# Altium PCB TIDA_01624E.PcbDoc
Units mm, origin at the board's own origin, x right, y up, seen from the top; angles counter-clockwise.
Board outline 19.05 x 30.89 mm, 2 copper layers (Top Layer, Bottom Layer), stack 0.239 mm thick; 33 components, 19 nets, 97 pads, 129 vias.
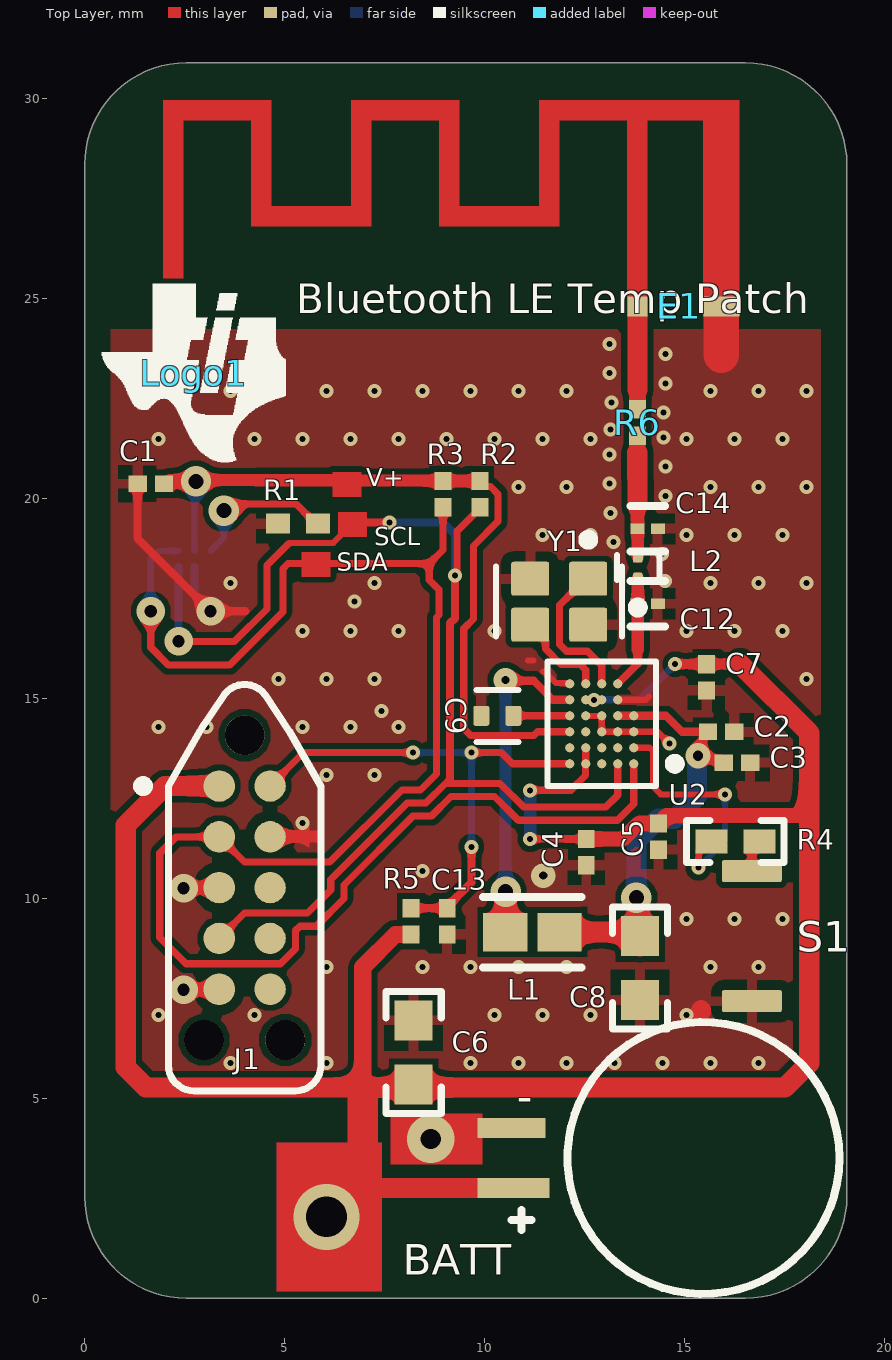
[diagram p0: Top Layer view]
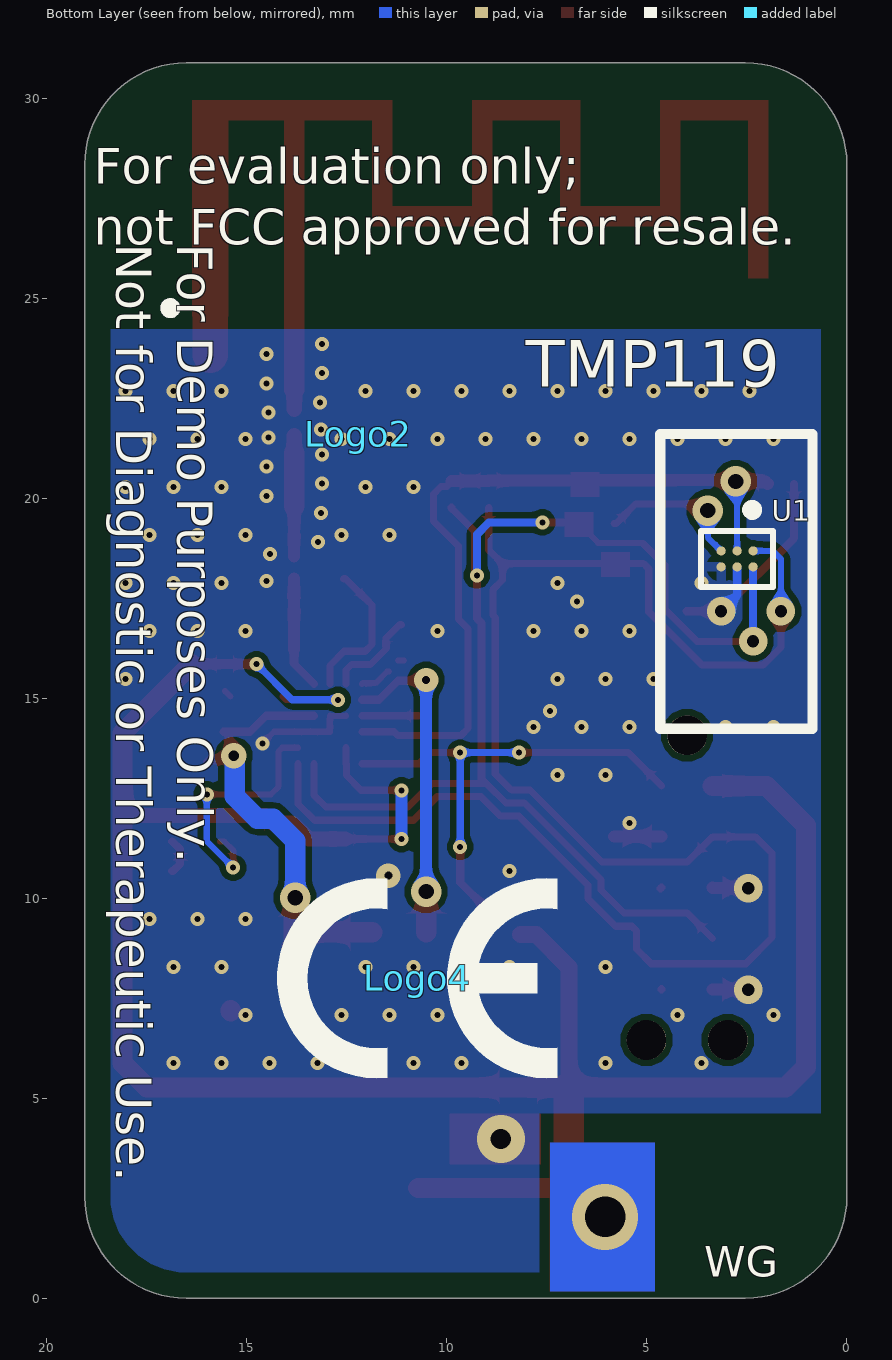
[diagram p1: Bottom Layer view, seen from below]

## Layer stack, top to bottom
Top Solder: solder mask 0.0254, Polymide, Dk 3.3
Top Layer: signal copper 0.0178
Stiffener: dielectric 0.127, Polyimide, Dk 4.2
Flex Substrate: core 0.0762, Polymide, Dk 3.3
Bottom Layer: signal copper 0.0178
Bottom Solder: solder mask 0.0254, Polyimide, Dk 3.3

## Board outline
0,2.54 0,28.345 cw(c2.54,28.345) 2.54,30.885 16.51,30.885 cw(c16.51,28.345) 19.05,28.345 19.05,2.54 cw(c16.51,2.54) 16.51,0 2.54,0 cw(c2.54,2.54)

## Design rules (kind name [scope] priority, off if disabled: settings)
AcuteAngle [All] p1: minimum=4.50000000000000E+0001 checktracksonly=FALSE
AssemblyTestPointUsage [All] p1: valid=2
BoardOutlineClearance BoardOutlineClearance_MountingHoles [OnCopper and InComponentClass('Mounting Holes')] p1 off: gap=1.016 ignorepadtopadclearanceinfootprint=FALSE
BoardOutlineClearance BoardOutlineClearance_Poly [OnCopper and IsPoly] p2: gap=0.635 ignorepadtopadclearanceinfootprint=FALSE
BoardOutlineClearance [OnCopper and Not InComponentClass('Logo') and not InComponentClass('FiducialMark') and not InRegion(1000,500,4000,800) and not InPoly] p3 off: gap=1.016 ignorepadtopadclearanceinfootprint=FALSE
Clearance Clearance_2 [InNamedPolygon('GND_L01_P002') vs InComponent('E1')] p1: gap=0 ignorepadtopadclearanceinfootprint=FALSE
Clearance Clearance_Keepouts [((IsTrack Or IsArc) And Not InPoly) And IsFree and IsKeepOut vs ((IsTrack Or IsArc) And Not InPoly) And IsFree and IsKeepOut] p2: gap=0 ignorepadtopadclearanceinfootprint=FALSE
Clearance Clearance_Poly [InPolygon] p3 off: gap=0.635 ignorepadtopadclearanceinfootprint=FALSE except(0: Arc-Hole Track-Hole SMDPad-Hole THPad-Hole Via-Hole Fill-Hole Poly-Hole Region-Hole Text-Hole)
Clearance [All] p4: gap=0.15 ignorepadtopadclearanceinfootprint=FALSE
ComponentClearance ComponentClearance_ant [InComponent('R6') vs InComponent('R7')] p1: gap=0 collisioncheckmode=3 verticalgap=0 showdistances=FALSE
ComponentClearance ComponentClearance_MountingHoles_FiducialMarks [InComponentClass('Mounting Holes') vs InComponentClass('FiducialMark')] p2: gap=1.27 collisioncheckmode=3 verticalgap=0.254 showdistances=FALSE
ComponentClearance ComponentClearance_Shunt [InComponentClass('Header') vs InComponentClass('Shunt')] p3: gap=0 collisioncheckmode=3 verticalgap=0 showdistances=FALSE
ComponentClearance ComponentClearance_Logo [InComponentClass('Logo')] p4: gap=0 collisioncheckmode=3 verticalgap=0 showdistances=FALSE
ComponentClearance ComponentClearance_ScrewToNut [(HasFootprint('NY PMS 440 0025 PH')) vs (HasFootprint('Keystone_1902C'))] p5: gap=0.127 collisioncheckmode=3 verticalgap=0.254 showdistances=FALSE
ComponentClearance ComponentClearance_MountingHoles [InComponentClass('Mounting Holes')] p6: gap=6.35 collisioncheckmode=3 verticalgap=2540 showdistances=FALSE
ComponentClearance ComponentClearance_SmallPassives [HasFootprint('0201*') or HasFootprint('0402*') or HasFootprint('0508') or HasFootprint('0603*') or HasFootprint('0612') or HasFootprint('0805*') or HasFootprint('0815*') or HasFootprint('0830*') or HasFootprint('1206*') or HasFootprint('1210*') or HasFootprint('1808*') or HasFootprint('1812*') or HasFootprint('1825*') or HasFootprint('2010*') or HasFootprint('2220*') or HasFootprint('2225*') or HasFootprint('2512*') or HasFootprint('2728*') or HasFootprint('3518*') vs HasFootprint('0201*') or HasFootprint('0402*') or HasFootprint('0508') or HasFootprint('0603*') or HasFootprint('0612') or HasFootprint('0805*') or HasFootprint('0815*') or HasFootprint('0830*') or HasFootprint('1206*') or HasFootprint('1210*') or HasFootprint('1808*') or HasFootprint('1812*') or HasFootprint('1825*') or HasFootprint('2010*') or HasFootprint('2220*') or HasFootprint('2225*') or HasFootprint('2512*') or HasFootprint('2728*') or HasFootprint('3518*')] p7: gap=0.38 collisioncheckmode=3 verticalgap=0.254 showdistances=FALSE
ComponentClearance ComponentClearance_THtoSMT [IsThruComponent vs IsSMTComponent] p8: gap=1.016 collisioncheckmode=3 verticalgap=0.762 showdistances=FALSE
ComponentClearance ComponentClearance_THtoTH [IsThruComponent vs IsThruComponent] p9: gap=0.381 collisioncheckmode=3 verticalgap=0.762 showdistances=FALSE
ComponentClearance [All] p10: gap=0.381 collisioncheckmode=3 verticalgap=0.254 showdistances=FALSE
DiffPairsRouting [All] p1: maxlimit=2.54 minlimit=0.254 mostfreqgap=0.254 substack1={58F8C5E5-8A2A-45DE-ADA6-7FDF080C0BA6} toplayer_{58f8c5e5-8a2a-45de-ada6-7fdf080c0ba6}_minwidth=0.381 toplayer_{58f8c5e5-8a2a-45de-ada6-7fdf080c0ba6}_maxwidth=0.381 toplayer_{58f8c5e5-8a2a-45de-ada6-7fdf080c0ba6}_prefwidth=0.381 bottomlayer_{58f8c5e5-8a2a-45de-ada6-7fdf080c0ba6}_minwidth=0.381 bottomlayer_{58f8c5e5-8a2a-45de-ada6-7fdf080c0ba6}_maxwidth=0.381 bottomlayer_{58f8c5e5-8a2a-45de-ada6-7fdf080c0ba6}_prefwidth=0.381 toplayer_minwidth=0.381 toplayer_maxwidth=0.381 toplayer_prefwidth=0.381 bottomlayer_minwidth=0.381 bottomlayer_maxwidth=0.381 bottomlayer_prefwidth=0.381 maxuncoupledlength=25.4
FabricationTestPointUsage TestPointUsage [All] p1: valid=2 allowmultiple=FALSE
FabricationTestpoint Testpoint [All] p1: side=3 testpointundercomponent=TRUE minsize=1.016 maxsize=2.54 preferedsize=1.524 minholesize=0 maxholesize=1.016 preferedholesize=0.813 testpointgrid=0.025 allowsidetop=TRUE allowsidebottom=TRUE usegrid=TRUE gridtolerance=0
FanoutControl Fanout_LCC [IsLCC] p1: bgadir=Out bgaviamode=Centered fanoutstyle=Auto fanoutdirection=Alternating viagrid=0.025 // Fanout_LCC (Default Rule)
FanoutControl Fanout_BGA [IsBGA] p2: bgadir=Out bgaviamode=Centered fanoutstyle=Auto fanoutdirection=Alternating viagrid=0.025 // Fanout_BGA (Default Rule)
FanoutControl Fanout_Default [All] p4: bgadir=Out bgaviamode=Centered fanoutstyle=Auto fanoutdirection=Alternating viagrid=0.025 // Fanout_Default (Default Rule)
FanoutControl Fanout_Small [(CompPinCount < 5)] p5: bgadir=Out bgaviamode=Centered fanoutstyle=Auto fanoutdirection=OutThenIn viagrid=0.025 // Fanout_Small (Default Rule)
HoleSize [All] p1: absolutevalues=TRUE maxlimit=6.375 minlimit=0.15 maxpercent=80.000 minpercent=20.000
MinimumAnnularRing MinimumAnnularRing_ThermalPadVias [IsVia and InAnyComponent] p1: minimumring=0.15
MinimumAnnularRing [All] p2: minimumring=0.1
MinimumSolderMaskSliver MinimumSolderMaskSliver_Logo [InComponentClass('Logo') vs InComponentClass('Logo')] p1: minsoldermaskwidth=0.018
MinimumSolderMaskSliver [All] p2: minsoldermaskwidth=0.051
PlaneConnect [All] p1: planeconnectstyle=Relief reliefexpansion=0.254 reliefentries=4 reliefconductorwidth=0.254 reliefairgap=0.254
PolygonConnect [All] p1: thpad.connectstyle=Relief thpad.reliefconductorwidth=0.254 thpad.reliefentries=4 thpad.polygonreliefangle="90 Angle" thpad.airgapwidth=0.254 smdpad.connectstyle=Relief smdpad.reliefconductorwidth=0.254 smdpad.reliefentries=4 smdpad.polygonreliefangle="90 Angle" smdpad.airgapwidth=0.254 via.connectstyle=Direct via.reliefconductorwidth=0.254 via.reliefentries=4 via.polygonreliefangle="90 Angle" via.airgapwidth=0.254
RoutingVias ThermalPadVias [IsVia and InAnyComponent] p1: holewidth=0.2 width=0.5 viastyle="Through Hole" minholewidth=0.2 minwidth=0.5 maxholewidth=0.33 maxwidth=0.6
RoutingVias [All] p2: holewidth=0.305 width=0.711 viastyle="Through Hole" minholewidth=0.15 minwidth=0.35 maxholewidth=1.016 maxwidth=1.651
ShortCircuit NoNet [IsComponentVia and not InAnyNet vs IsComponentPad and not InAnyNet] p1: allowed=TRUE
ShortCircuit [All] p2: allowed=FALSE
SilkToBoardRegionClearance [Not ((IsComment or IsDesignator) And (Hide <> 'False')) and not InRegion(1000,500,4000,800)] p1:
SilkToSilkClearance SilkToSilkClearance_Pb-FreeLogo [HasFootprint('FCC_disclaimer') vs HasFootprint('TI_Symbol_Overlay_Small')] p1: silktosilkclearance=0
SilkToSilkClearance SilkToSilkClearance_Pb-FreeLogo_1 [(HasFootprint('Pb-Free_Overlay_Medium') OR HasFootprint('Pb-Free_Overlay_Small')) vs (HasFootprint('Pb-Free_Overlay_Medium') OR HasFootprint('Pb-Free_Overlay_Small'))] p2: silktosilkclearance=0
SilkToSilkClearance [All] p3: silktosilkclearance=0.102
SilkToSolderMaskClearance "Silk to Solder Mask Opening" [All] p1: minsilkscreentomaskgap=0.038 clearancetoexposedcopper=FALSE
SolderMaskExpansion SolderMaskExpansion_via [IsVia] p1: expansion=-0.203 istentingtop=FALSE
SolderMaskExpansion [All] p2: expansion=0.05 istentingtop=FALSE
Width [All] p1: maxlimit=0.889 minlimit=0.089 preferedwidth=0.203 substack1={58F8C5E5-8A2A-45DE-ADA6-7FDF080C0BA6} toplayer_{58f8c5e5-8a2a-45de-ada6-7fdf080c0ba6}_minwidth=0.102 bottomlayer_{58f8c5e5-8a2a-45de-ada6-7fdf080c0ba6}_minwidth=0.102 checkconnectedcopper=TRUE
14 further rules are at their usual default settings.

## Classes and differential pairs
component class AssemblyNote: ZZ1 ZZ2 ZZ3
component class Logo: Logo1

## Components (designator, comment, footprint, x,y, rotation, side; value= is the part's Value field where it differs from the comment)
BATT "MS621FE-FL11E" SEIK-MS621FE-FL11E-2_V 15.465,3.505 r180 top
C1 "GRM033C71A104KE14D" 0201 1.648,20.361 r0 top value=0.1uF
C2 "GRM033C71A104KE14D" 0201 15.91,14.162 r180 top value=0.1uF
C3 "GRM033C71A104KE14D" 0201 16.303,13.386 r180 top value=0.1uF
C4 "GRM033C71A104KE14D" 0201 12.535,11.151 r90 top value=0.1uF
C5 "GRM033C71A104KE14D" 0201 14.344,11.54 r90 top value=0.1uF
C6 "GRM188Z71A106KA73D" 0603 8.217,6.147 r270 top
C7 "GRM033C71A104KE14D" 0201 15.541,15.524 r90 top value=0.1uF
C8 "GRM188Z71A106KA73D" 0603 13.879,8.255 r90 top
C9 "GRM155Z71A105KE01D" FP-GRM155Z71A105KE01D_0402-MFG 10.31,14.562 r180 top value=1µF
C12 "GRM0335C1H1R5BA01J" FP-GRM033-0_03-IPC_C 14.072,17.365 r0 top
C13 "GRM033C71A104KE14D" 0201 9.06,9.423 r90 top value=0.1uF
C14 "GRM0335C1H1R5BA01J" FP-GRM033-0_03-IPC_C 14.072,19.237 r0 top
E1 "ANTENNA_IIFA" ANTENNA_IIFA 15.915,24.546 r180 top net-tie
J1 "DNP - Nothing to buy or mount" Tag_TC2050-NL 3.995,10.265 r0 top
L1 "LQM18DN100M70L" FP-LQM18DN_70-IPC_B 11.187,9.153 r0 top
L2 "LQP03TN2N8B02J" "FP-LQP03TN2N8B02J_0201 (0603)-MFG" 13.823,18.267 r90 top value=2.8nH
Logo1 "Texas Instruments" TI_Symbol_Overlay_Small 2.725,23.127 r0 top
Logo2 "FCC disclaimer" FCC_disclaimer 12.217,21.612 r180 bottom
Logo4 "CE Mark" CE_Mark_5mm 10.74,7.999 r180 bottom
R1 "RC0402JR-070RL" 0402L 5.325,19.364 r180 top value=0
R2 "RC0201FR-7D6K98L" 0201 9.881,20.101 r270 top value=6.98k
R3 "RC0201FR-7D6K98L" 0201 8.953,20.101 r270 top value=6.98k
R4 "ERJ-2RKF2401X" 0402 16.264,11.419 r0 top value=2.40k
R5 "RC0201JR-7D100KL" 0201 8.153,9.423 r90 top value=100k
R6 "CRCW02010000Z0ED" 0201 13.814,21.894 r90 top value=0
S1 "TL3780AF330QG" SW_TL3780 16.675,9.053 r270 top
U1 "TMP119AIYBGR" YBG0006-C01-MFG 2.742,18.484 r270 bottom
U2 "CC2340R53E0YBGR" YBG0028-C01-MFG 12.923,14.362 r180 top
Y1 "TZ3908AAAO43" FP-TZ3908AAAO43_SMT4_2MM05_1MM65-MFG 11.86,17.413 r180 top
ZZ1 "These assemblies are ESD sensitive, ESD precautions shall be observed." AssemblyNote -36.17,53.797 r0 top
ZZ2 "These assemblies must be clean and free from flux and all contaminants. Use of no clean flux is not acceptable." AssemblyNote -36.195,50.902 r0 top
ZZ3 "These assemblies must comply with workmanship standards IPC-A-610 Class 2, unless otherwise specified." AssemblyNote -36.246,47.981 r0 top

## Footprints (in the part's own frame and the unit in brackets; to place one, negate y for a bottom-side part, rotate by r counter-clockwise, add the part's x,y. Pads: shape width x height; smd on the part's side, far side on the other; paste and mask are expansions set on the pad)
0201 [mm] "Data from Kemet datasheet CC101_COM dated 7/28/11"
  rect 0.46x0.42 smd mask+0.048: 1(-0.33,0) 2(0.33,0)
  body extent -0.31,-0.16 0.31,0.16, height 0.26
0402 [mm] "0402 from SM-752 data"
  rect 0.8x0.6 smd: 1(-0.6,0) 2(0.6,0)
  silkscreen extent -1.22,-0.52 1.22,0.52, body extent -0.55,-0.3 0.55,0.3, height 0.6
0402L [mm] "0402 from SM-752 data"
  rect 0.6x0.5 smd: 1(-0.5,0) 2(0.5,0)
  body extent -0.55,-0.3 0.55,0.3, height 0.6
0603 [mm] "0603 from SM-752 data"
  rect 1x0.95 smd: 1(-0.8,0) 2(0.8,0)
  silkscreen extent -1.52,-0.69 1.52,0.69, body extent -0.87,-0.47 0.87,0.47, height 1
ANTENNA_IIFA [mm] "PCB Antenna, 2-Leads"
  rect 0.9x0.5 smd paste-1 mask-1: 1(0,-0.25)
  rect 0.5x0.5 smd paste-1 mask-1: 2(2.1,-0.25)
  Top Layer region: -0.45,0 -0.45,-5.4 4.55,-5.4 4.55,-2.76 6.55,-2.76 6.55,-5.4 9.25,-5.4 9.25,-2.76 11.25,-2.76 11.25,-5.4 13.95,-5.4 13.95,-0.96 13.45,-0.96 13.45,-4.9 11.75,-4.9 11.75,-2.26 8.75,-2.26 8.75,-4.9 7.05,-4.9 7.05,-2.26 4.05,-2.26 4.05,-4.9 2.35,-4.9 2.35,0 1.85,0 1.85,-4.9 0.45,-4.9 0.45,0
AssemblyNote [mm] "Assembly Note"
CE_Mark_5mm [mm] "Minimum text height for CE Mark"
  silkscreen extent -3.5,-2.5 3.5,2.5
FCC_disclaimer [mm]
FP-GRM033-0_03-IPC_C [mm]
  rect 0.354x0.263 smd paste+0 mask+0: 1(-0.254,0) 2(0.254,0)
  silkscreen extent -0.43,-0.57 0.43,0.57, body extent -0.53,-0.27 0.53,0.27, height 0.25
FP-GRM155Z71A105KE01D_0402-MFG [mm]
  rrect25% 0.4x0.5 smd paste+0 mask+0: 1(-0.4,0) 2(0.4,0)
  silkscreen extent -0.53,-0.65 0.53,0.65, body extent -0.7,-0.38 0.7,0.38, height 0.25
FP-LQM18DN_70-IPC_B [mm]
  rect 1.106x0.958 smd paste+0 mask+0: 1(-0.676,0) 2(0.676,0)
  silkscreen extent -1.23,-0.88 1.23,0.88, body extent -1.48,-0.73 1.48,0.73, height 0.25
"FP-LQP03TN2N8B02J_0201 (0603)-MFG" [mm]
  rrect40% 0.3x0.25 smd paste+0 mask+0: 1(-0.275,0) 2(0.275,0)
  silkscreen extent -1.12,-0.54 0.32,0.53, body extent -0.53,-0.27 0.53,0.27, height 0.25
FP-TZ3908AAAO43_SMT4_2MM05_1MM65-MFG [mm]
  rrect12% 0.95x0.85 smd paste+0 mask+0: 1(-0.725,-0.575) 2(0.725,-0.575) 3(0.725,0.575) 4(-0.725,0.575)
  silkscreen extent -1.58,-1.67 1.58,0.87, body extent -1.3,-1.1 1.3,1.1, height 0.25
SEIK-MS621FE-FL11E-2_V [mm] "SMD, 2-Leads, Diameter 6.8mm"
  rect 1.8x0.5 smd: 1(4.75,0.75)
  rect 1.7x0.5 smd: 2(4.8,-0.75)
  silkscreen extent -3.4,-3.4 4.8,3.4, body extent -3.4,-3.4 4.35,3.4, height 2.7
SW_TL3780 [mm] "SMD, 2-Leads, Body 3x2mm"
  rrect18% 0.55x1.5 smd: 1(-1.625,0) 2(1.625,0)
  body extent -1.63,-1.12 1.63,1.12, height 0.7
Tag_TC2050-NL [mil] "Footprint for Tag-Connect TC2050 No-Legs cables"
  round 31 smd paste-15.75: 1(-25,100) 2(-25,50) 3(-25,0) 4(-25,-50) 5(-25,-100) 6(25,-100) 7(25,-50) 8(25,0) 9(25,50) 10(25,100)
  round 39 hole 39 unplated: MH1(0,150) MH2(-40,-150) MH3(40,-150)
  silkscreen extent -105,-200 75,200
TI_Symbol_Overlay_Small [mm]
  silkscreen extent -2.3,-2.23 2.3,2.24
YBG0006-C01-MFG [mm]
  round 0.23 smd paste-1000 mask+0.05: A1(-0.2,0.4) A2(0.2,0.4) B1(-0.2,0) B2(0.2,0) C1(-0.2,-0.4) C2(0.2,-0.4)
  silkscreen extent -1.35,-0.9 0.7,0.9, body extent -0.48,-0.74 0.48,0.74, height 0.53
YBG0028-C01-MFG [mm]
  round 0.23 smd paste-1000 mask+0.05: A1(-0.8,1) A2(-0.4,1) A3(0,1) A4(0.4,1) A5(0.8,1) B1(-0.8,0.6) B2(-0.4,0.6) B3(0,0.6) B4(0.4,0.6) B5(0.8,0.6) C1(-0.8,0.2) C2(-0.4,0.2) C3(0,0.2) C4(0.4,0.2) C5(0.8,0.2) D1(-0.8,-0.2) D2(-0.4,-0.2) D3(0,-0.2) D4(0.4,-0.2) D5(0.8,-0.2) E2(-0.4,-0.6) E3(0,-0.6) E4(0.4,-0.6) E5(0.8,-0.6) F2(-0.4,-1) F3(0,-1) F4(0.4,-1) F5(0.8,-1)
  silkscreen extent -1.95,-1.56 1.35,1.56, body extent -1.6,-1.81 1.6,1.81, height 0.25

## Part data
BATT: library part CMP-2000-05342-1, "MS Lihium Rechargeable Battery, 3 V, -20 to 60 degC, Tray", Capacity=5.5mAh, Manufacturer=SeikoInstruments, Output Voltage=3V
C1 C2 C3 C4 C5 C7 C13: library part CMP-0064969-1, "CAP, CERM, 0.1 uF, 10 V,+/- 10%, X7S, 0201", Cap_Case=0201, Manufacturer=MuRata, Supplier Part Number 1=490-14450-1-ND, TempCo=X7S, Tolerance_%=10%, Value1=Unknown, Value2=10V, ValueDisplayed=0.1uF
C6 C8: library part CMP-0087107-2, "Chip Multilayer Ceramic Capacitors for General Purpose", Manufacturer=Murata, TempCo=15%, Tolerance_%=10%
C9: library part CMP-0092999-1, "Chip Multilayer Ceramic Capacitors for General Purpose, 0402, 1.0uF, X7R, 15%, 10%, 10V", Manufacturer=Murata, Operating Temperature Range="-55°C to +125°C", TempCo=15%, Temperature Characteristic=X7R, Tolerance_%=10%, ValueDisplayed=1.0uF
C12 C14: library part CMP-06035-002174-1, "Chip Multilayer Ceramic Capacitors for General Purpose, 0201, 1.5pF, C0G, 30ppm/°C, 0.1pF, 50V", Capacitance=1.5pF, Case Code (Imperial)=0201, Case Code (Metric)=0603, Dielectric=C0G, Max Operating Temperature=125°C, Min Operating Temperature=-55°C, Package Quantity=50000, Voltage Rating=50V
E1: library part CMP-0001736-1, "PCB Antenna.  There is nothing to buy or mount.", Manufacturer=N/A
J1: library part CMP-0075101-1, "Footprint for Tag-Connect TC2050 No-Legs cables", Manufacturer=Tag-Connect, PartNumber=TC2050-IDC-NL-FP
L1: library part CMP-06042-017052-1, "Multilayer type Inductor for Power Lines 10uH ±20% @1MHz, 300mA, Max DCR 1.365Ω, SRF 32MHz"
L2: library part CMP-0001349-1, "Film type RF Inductor 2.8nH ±0.1nH 500mA 0.2Ω 0201 (0603)", Manufacturer=Murata, Operating Temperature Range="-55°C to +125°C", Self Resonant Frequency=9.5GHz, Test Frequency=500MHz, Tolerance_%=0.1nH
Logo1: library part CMP-0074838-1, "Texas Instrument Corporate Signature"
Logo2: library part CMP-0074847-1, "FCC_disclaimer"
Logo4: library part CMP-0074844-1
R1: library part CMP-0027004-2, "RES, 0, 5%, 0.063 W, 0402", Manufacturer="Yageo America", Power_W=63mW, Supplier Part Number 1=311-0.0JRCT-ND, TempCo="200 ppm/C", Tolerance_%=5%, Value2=0.063W, Value_Code=0000, ValueDisplayed=0
R2 R3: library part CMP-0028058-1, "RES, 6.98 k, 1%, 0.05 W, 0201", Manufacturer="Yageo America", Power_W=50mW, Supplier Part Number 1=603-RC0201FR-7D6K98L, TempCo="200 ppm/C", Tolerance_%=1%, Value2=0.05W, Value_Code=6k98, ValueDisplayed=6.98k
R4: library part CMP-0026685-1, "RES, 2.40 k, 1%, 0.1 W, AEC-Q200 Grade 0, 0402", Manufacturer=Panasonic, Power_W=100mW, Supplier Part Number 1=P2.40KLCT-ND, TempCo="100 ppm/C", Tolerance_%=1%, Value2=0.1W, Value_Code=2k40, ValueDisplayed=2.40k
R5: library part CMP-0027184-1, "RES, 100 k, 5%, 0.05 W, 0201", Manufacturer="Yageo America", Power_W=50mW, Supplier Part Number 1=603-RC0201JR-7D100KL, TempCo="200 ppm/C", Tolerance_%=5%, Value2=0.05W, Value_Code=100k
R6: library part CMP-0027008-4, "RES, 0, 5%, 0.05 W, 0201", Manufacturer=Vishay-Dale, Power_W=50mW, Supplier Part Number 1=72M6743, TempCo=ppm/C, Tolerance_%=5%, Value2=0.05W, Value_Code=0000, ValueDisplayed=0
S1: library part CMP-0084104-1, "Switch, SPST-NO, 0.05 A, 12 VDC, SMT", CurrentRating_mA=50A, Manufacturer=E-Switch
U1: library part CMP-0049997-1, "High-Accuracy, Low-Power, Digital Temperature Sensor With SMBus™- and I2C-Compatible Interface", Manufacturer="Texas Instruments", Max Supply Voltage=5.5V, Min Supply Voltage=1.7V, Operating Supply Current=135uA, Operating Temperature Range="-55°C to +150°C"
U2: library part CMP-0122602-1, "Family SimpleLink™ Wireless MCU, DSBGA28", Frequency_Fixed=48MHz, Manufacturer="Texas Instruments", Max Supply Voltage=3.8V, Min Supply Voltage=1.71V, Operating Temperature Range="-40°C to +125°C"
Y1: library part CMP-0001392-1, "Crystal Unit SMD 2.0x1.6 48.0MHz", Frequency Stability=30ppm, Frequency Tolerance=5ppm, Frequency_Fixed=48MHz, Load Capacitance=7pF, Manufacturer="TAI-SAW Thechnology", Operating Temperature Range="-40°C to +125°C"
ZZ1: library part CMP-0077236-1
ZZ2: library part CMP-0077237-1
ZZ3: library part CMP-0077238-1

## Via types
v1: diameter 0.35, hole 0.15, Top Layer to Bottom Layer, 101 vias
v2: diameter 0.35, hole 0.15, Top Layer to Bottom Layer, tented both sides, 14 vias
v3: diameter 0.711, hole 0.305, Top Layer to Bottom Layer, tented both sides, 5 vias
v4: diameter 0.762, hole 0.381, Top Layer to Bottom Layer, tented both sides, 4 vias
v5: diameter 0.61, hole 0.203, Top Layer to Bottom Layer, tented both sides, 2 vias
v6: diameter 1.65, hole 1.016, Top Layer to Bottom Layer, 1 vias
v7: diameter 1.194, hole 0.508, Top Layer to Bottom Layer, 1 vias
v8: diameter 0.635, hole 0.254, Top Layer to Bottom Layer, tented both sides, 1 vias

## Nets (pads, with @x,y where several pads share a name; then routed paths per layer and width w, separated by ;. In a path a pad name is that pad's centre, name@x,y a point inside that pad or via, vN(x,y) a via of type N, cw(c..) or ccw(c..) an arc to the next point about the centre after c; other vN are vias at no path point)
ANT: C12.1 L2.1 U2.F2 | length 2.8
  Top Layer w0.203: U2.F2 13.823,15.862 13.823,16.212
  Top Layer w0.305: 13.823,16.212 L2.1
DCDC_SW: L1.1 U2.E5 | length 8.1
  Top Layer w0.203: v5(10.517,15.456) 10.537,15.437 11.222,15.437 11.697,14.962 U2.E5
  Top Layer w0.508: L1.1 v4(10.517,10.166)
  Bottom Layer w0.305: v4(10.517,10.166) v5(10.517,15.456)
GND: BATT.2 C1.1 C2.1 C3.1 C4.1 C5.1 C6.1 C7.1 C8.1 C9.2 C12.2 C13.1 C14.2 E1.1 J1.3 J1.5 J1.9 R1.2 S1.2 U1.B2 U1.C2 U2.C1 U2.C2 U2.C3 U2.D3 U2.D4 U2.E2 U2.F5 Y1.2 Y1.4 | length 14.6
  Top Layer w0.152: 11.074,15.942 11.217,15.942 ; 11.454,15.669 11.49,15.669 11.782,15.377 12.108,15.377 U2.F5 ; U2.D4 12.524,14.561 12.922,14.561 U2.D3 U2.C3 U2.C2 U2.C1 14.321,14.162 v2(14.61,13.872) ; U2.E2 14.026,14.962 14.104,15.04 ; C7.1@15.407,15.04 C7.1@15.541,15.174
  Top Layer w0.203: C1.1 1.318,18.999 v3(3.142,17.174) 4.011,17.174
  Top Layer w0.305: v3(2.467,7.712) 2.474,7.719 J1.5@3.353,7.719 ; v3(2.467,10.252) 2.474,10.259 3.353,10.259 J1.3 ; J1.9@4.636,11.542 5.818,11.542
  Top Layer w0.508: 15.403,7.176 15.403,7.201
  Top Layer w0.889: 15.915,23.581 E1.1@15.915,24.546
  Bottom Layer w0.203: U1.B2 2.742,17.574 v3(3.142,17.174)
  Bottom Layer w0.381: v3@2.46,7.719 v3(2.467,7.712)
  other v1: 3.64,5.878 6.04,5.878 9.64,5.878 10.84,5.878 12.04,5.878 13.24,5.878 14.44,5.878 15.64,5.878 16.84,5.878 1.84,7.078 4.24,7.078 10.24,7.078 11.44,7.078 12.64,7.078 15.04,7.078 6.04,8.278 8.44,8.278 9.64,8.278 10.84,8.278 12.04,8.278 15.64,8.278 16.84,8.278 15.04,9.478 16.24,9.478 17.44,9.478 8.44,10.678 5.44,11.878 6.04,13.078 7.24,13.078 1.84,14.278 3.04,14.278 5.44,14.278 6.64,14.278 7.84,14.278 4.84,15.478 6.04,15.478 7.24,15.478 18.04,15.478 5.44,16.678 6.64,16.678 7.84,16.678 10.24,16.678 15.04,16.678 16.24,16.678 17.44,16.678 3.64,17.878 7.24,17.878 15.64,17.878 16.84,17.878 18.04,17.878 14.503,17.93 14.425,18.601 13.22,18.906 11.44,19.078 12.64,19.078 15.04,19.078 16.24,19.078 17.44,19.078 13.146,19.633 14.513,20.058 10.84,20.278 12.04,20.278 15.64,20.278 16.84,20.278 18.04,20.278 13.119,20.364 14.511,20.789 13.117,21.095 1.84,21.478 3.04,21.478 4.24,21.478 5.44,21.478 6.64,21.478 7.84,21.478 9.04,21.478 10.24,21.478 11.44,21.478 12.64,21.478 15.04,21.478 16.24,21.478 17.44,21.478 14.461,21.519 13.141,21.719 14.461,22.141 13.167,22.398 2.44,22.678 3.64,22.678 4.84,22.678 6.04,22.678 7.24,22.678 8.44,22.678 9.64,22.678 10.84,22.678 12.04,22.678 15.64,22.678 16.84,22.678 18.04,22.678 14.51,22.871 13.118,23.127 14.511,23.602 13.118,23.858
  other v2: 7.422,14.679 6.743,17.413
  other v5: 11.461,10.565
  other v7: 8.649,3.981
JTAG_RST: C13.2 J1.10 R5.2 U2.A5 | length 13
  Top Layer w0.178: J1.10 5.464,13.64 v2(8.198,13.64) ; v2(9.666,13.64) 10.412,13.64 10.69,13.362 U2.A5
  Top Layer w0.203: R5.2 9.041,9.753 9.06,9.772 9.06,9.792 9.666,10.398 v2(9.666,11.285)
  Bottom Layer w0.178: v2(8.198,13.64) v2(9.666,13.64) v2(9.666,11.285)
JTAG_SDWIO_SDA: J1.2 R3.2 U1.A1 U2.A1 | length 44.9
  Top Layer w0.178: v3(1.648,17.174) 1.648,16.274 2.095,15.827 3.615,15.827 4.951,17.163 4.951,18.238 5.079,18.366 8.611,18.366 ; R3.2 8.953,18.708 8.611,18.366 ; U2.A1 13.723,12.36 13.313,11.95 10.836,11.95 10.241,12.545 9.152,12.545 8.659,12.052 8.197,12.052 6.476,10.331 6.476,9.991 5.785,9.3 5.376,9.3 5.262,9.186 5.262,8.733 4.892,8.363 2.528,8.363 1.873,9.018 1.873,11.124 2.284,11.535 3.333,11.535 3.346,11.522 J1.2 3.992,10.903 6.12,10.903 7.925,12.707 8.388,12.707 8.79,13.11 8.79,17.019 8.851,17.08 8.851,17.713 8.611,17.953 8.611,18.366
  Bottom Layer w0.152: v3(1.648,17.174) 1.648,18.485 1.847,18.684 U1.A1
JTAG_SWDCLK_SCL: J1.4 R2.2 U1.A2 U2.A2 | length 31.9
  Top Layer w0.152: 5.106,18.878 5.11,18.882 6.215,18.882 6.729,19.396
  Top Layer w0.178: v3(2.342,16.423) 3.745,16.423 4.553,17.231 4.553,18.324 5.102,18.873 5.11,18.873 ; J1.4 3.992,9.628 5.57,9.628 6.148,10.206 6.148,10.467 8.061,12.38 8.524,12.38 9.017,12.873 ; 9.047,12.873 10.377,12.873 10.972,12.277 13.024,12.277 13.323,12.576 U2.A2 ; v2(9.251,18.069) 9.305,18.123 9.305,19.175 R2.2@9.881,19.751
  Top Layer w0.203: 6.729,19.396 v2(7.611,19.396) ; 9.047,12.885 9.131,12.969 9.131,16.878 9.251,16.998 v2(9.251,18.069) ; R2.2@9.881,19.751 R2.2
  Bottom Layer w0.203: v3(2.342,16.423) U1.A2 ; v2(7.611,19.396) 8.953,19.396 9.251,19.098 v2(9.251,18.069)
JTAG_TDI: J1.8 | length 0
  Top Layer w0.203: J1.8 J1.8@4.655,10.24
JTAG_TDO: J1.6 | length 0
  Top Layer w0.203: J1.6 J1.6@4.633,7.722
NetC9_1: C9.1 U2.D5 | length 1.4
  Top Layer w0.178: C9.1 U2.D5
NetC14_1: C14.1 L2.2 R6.1 | length 3.1
  Top Layer w0.305: 13.817,19.802 C14.1 13.823,19.232 L2.2
  Top Layer w0.381: 13.814,21.056 R6.1@13.814,21.564
  Top Layer w0.508: 13.814,21.144 13.817,19.802
NetE1_2: E1.2 R6.2 | length 2.6
  Top Layer w0.381: R6.2 13.814,22.707
  Top Layer w0.508: 13.814,22.707 E1.2
NetR1_1: R1.1 U1.C1 | length 3.8
  Top Layer w0.152: v4@3.475,19.675 v4@3.484,19.684
  Top Layer w0.178: v4(3.476,19.692) 3.634,19.692 3.798,19.856 5.283,19.856 5.775,19.364 R1.1
  Bottom Layer w0.152: U1.C1 3.475,19.016 v4@3.475,19.675
NetR4_2: R4.2 S1.1 | length 0.9
  Top Layer w0.203: S1.1@16.864,10.678 16.848,10.678 16.675,10.851 16.675,11.229 R4.2
V_TMP: C1.2 R2.1 R3.1 U1.B1 U2.C5 | length 19.8
  Top Layer w0.178: R2.1 9.881,20.411 10.002,20.29 10.143,20.29 10.332,20.101 10.332,19.423 9.713,18.805 9.713,16.979 9.471,16.737 9.471,14.242 9.641,14.073 11.23,14.073 11.319,14.162 U2.C5
  Top Layer w0.254: 6.631,20.448 6.648,20.465
  Top Layer w0.305: C1.2 C1.2@2.019,20.402 ; C1.2@2.035,20.418 C1.2@2.019,20.402 ; C1.2@2.121,20.457 4.279,20.457 4.287,20.448 6.631,20.448 8.953,20.436 R2.1 ; v4@2.787,20.411 2.777,20.402 C1.2@2.019,20.402
  Bottom Layer w0.152: U1.B1 v4@2.742,20.284
  other v4: 2.779,20.419
VCC: BATT.1 C4.2 C5.2 C6.2 C7.2 J1.1 R5.1 U2.A4 U2.B4 U2.E3 U2.E4 | length 62.2
  Top Layer w0.178: v2(11.135,11.481) C4.2 ; v2(11.135,12.7) 12.147,12.7 12.513,13.066 12.513,13.352 U2.A4 U2.B4
  Top Layer w0.254: v2(14.76,15.854) C7.2 16.385,15.854
  Top Layer w0.381: 6.883,2.729 6.909,2.755 ; C4.2 12.935,11.481 13.451,11.48 13.84,11.87 C5.2 14.344,11.89 14.363,11.909 14.383,11.909 14.542,12.068 17.802,12.068 18.107,12.373
  Top Layer w0.432: 6.949,5.271 6.949,8.275 7.767,9.093 R5.1
  Top Layer w0.508: J1.1 1.999,12.805 1.021,11.828 1.021,5.774 1.524,5.271 6.949,5.271 6.95,5.271 17.504,5.271 18.107,5.874 18.107,12.373 18.107,14.132 16.385,15.854 ; 6.582,2.692 6.645,2.755 6.909,2.755 BATT.1 ; 6.883,2.729 6.92,2.692
  Top Layer w0.762: 6.95,3.723 6.95,5.271
  Bottom Layer w0.178: v2(12.723,14.962) 13.868,14.962 v2(14.76,15.854)
  Bottom Layer w0.305: v2(11.135,11.481) v2(11.135,12.7)
  other v6: 6.042,2.034
VDDR: C2.2 C3.2 C8.2 L1.2 U2.D1 U2.D2 | length 10.9
  Top Layer w0.203: U2.D2 U2.D1 14.524,14.562 14.924,14.162 C2.2@15.56,14.162 ; v8@15.451,13.804 15.451,14.054 C2.2@15.56,14.162 ; C2.2 C2.2@15.56,14.162
  Top Layer w0.254: v8@15.526,13.469 15.89,13.469 C3.2
  Top Layer w0.508: L1.2 13.658,9.153 13.835,8.977 13.835,8.845 C8.2@13.879,8.801 ; v4(13.79,10.014) 13.835,9.97 C8.2@13.835,9.055
  Bottom Layer w0.508: v4(13.79,10.014) 13.79,11.441 14.338,11.989 14.744,11.989 15.304,12.549 15.304,13.539 v8(15.328,13.564)
WAKE: R4.1 U2.B1 | length 6.2
  Top Layer w0.152: U2.B1 14.117,13.762 14.206,13.673 14.206,12.789 14.397,12.598 v2(16.002,12.598) ; v2(15.34,10.763) 15.34,11.195 15.564,11.419 R4.1
  Bottom Layer w0.152: v2(15.34,10.763) 16.002,11.425 v2(16.002,12.598)
X48M_N: U2.F3 Y1.1 | length 3.7
  Top Layer w0.178: Y1.1 12.535,17.988 12.021,17.474 12.013,17.474 11.871,17.332 11.871,16.344 12.041,16.174 12.568,16.174 12.923,15.819 U2.F3
X48M_P: U2.F4 Y1.3 | length 2.4
  Top Layer w0.178: Y1.3 11.185,16.838 11.521,16.502 11.521,16.23 11.905,15.846 12.387,15.846 12.523,15.71 U2.F4
pads on no net: J1.7 J1.MH1 J1.MH2 J1.MH3 U2.A3 U2.B2 U2.B3 U2.B5 U2.C4

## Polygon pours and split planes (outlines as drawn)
GND on Bottom Layer "BOTTOM_LAYER_GND_P000" (solid, remove dead copper, pour order 0): -0.508,4.623 -0.508,24.22 19.05,24.22 19.05,4.623 19.05,0.178 7.696,0.178 7.696,4.623
GND on Top Layer "TOP_LAYER_GND_P002" (solid, remove dead copper, pour order 2): 19.05,24.22 19.05,5.185 -0.508,5.185 -0.508,24.22

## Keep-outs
Keep-Out Layer:
  text ".Layer_Name" at -31.928,-42.964 h1.52

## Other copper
Top Layer:
  region net VCC: 7.422,0.178 7.422,3.889 4.801,3.889 4.801,0.178
  region net GND: 9.93,3.353 9.93,4.609 7.653,4.609 7.653,3.353
  region net JTAG_SWDCLK_SCL: 6.341,19.653 7.052,19.653 7.052,19.044 6.341,19.044
  region net V_TMP: 6.193,20.653 6.904,20.653 6.904,20.044 6.193,20.044
  region net JTAG_SDWIO_SDA: 5.426,18.653 6.137,18.653 6.137,18.044 5.426,18.044
  text "'.PRJ_Number'" at 24.371,-37.812 h1.52
  text ".Layer_Name" at -31.928,-42.964 h1.52
Bottom Layer:
  region net VCC: 4.801,0.178 4.801,3.889 7.417,3.889 7.417,0.178
  text "'.PRJ_Number'" at 24.371,-37.812 h1.52
  text ".Layer_Name" at -31.928,-42.964 h1.52

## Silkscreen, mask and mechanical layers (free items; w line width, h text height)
Top Overlay:
  text "Bluetooth LE Temp Patch" at 5.283,24.369 h1.27
  text "V+" at 7.031,20.152 h0.76
  text "SCL" at 7.24,18.672 h0.76
  text "SDA" at 6.3,18.044 h0.76
  text "-" at 11.201,5.258 h0.8 r180
  text "'.PRJ_Number'" at 24.371,-37.812 h1.52
  text ".Layer_Name" at -31.928,-42.964 h1.52
Bottom Overlay:
  lines w0.254: 0.856,14.239 4.666,14.239 4.666,21.605 0.856,21.605 0.856,14.239
  text "For Demo Purposes Only.   / Not for Diagnostic or Therapeutic Use." at 18.567,26.365 h1.52 r90
  text "TMP119" at 8.027,22.398 h2
  text "WG" at 3.563,0.533 h0.76
  text "'.PRJ_Number'" at 24.371,-37.812 h1.52
  text ".Layer_Name" at -31.928,-42.964 h1.52
Top Paste:
  text ".Layer_Name" at -31.928,-42.964 h1.52
Bottom Paste:
  text ".Layer_Name" at -31.928,-42.964 h1.52
Top Solder:
  text "'.PRJ_Number'" at 24.371,-37.812 h1.52
  text ".Layer_Name" at -31.928,-42.964 h1.52
  text ".Layer_Name" at -31.928,-42.964 h1.52
Bottom Solder:
  text "'.PRJ_Number'" at 24.371,-37.812 h1.52
  text ".Layer_Name" at -31.928,-42.964 h1.52
Drill Guide:
  text ".Layer_Name" at -31.928,-42.964 h1.52
M1 Board Outline:
  the board outline again, w0.254
  text ".Layer_Name" at -31.928,-42.964 h1.52
M2 Board Dimensions:
  rectangle: -43.409,-31.318 -33.884,-28.143
  rectangle: -46.584,-28.143 -43.409,-24.968
  lines w0.178: -46.584,-28.143 -21.184,-28.143 ; -46.584,-24.968 -46.584,-31.318 -21.184,-31.318 -21.184,-24.968 ; -45.872,-24.968 -20.472,-24.968 ; -43.409,-31.318 -43.409,-24.968 ; -40.234,-31.318 -40.234,-24.968 ; -33.884,-31.318 -33.884,-24.968 ; -27.534,-31.318 -27.534,-24.968
  text "'.PRJ_Number'" at 24.371,-37.812 h1.52
  text ".Layer_Name" at -31.928,-42.964 h1.52
M3 3D STEP Top:
  text ".Layer_Name" at -31.928,-42.964 h1.52
M4 3D STEP Bottom:
  text ".Layer_Name" at -31.928,-42.964 h1.52
M5 Assembly Top:
  lines w0.254: -54,-44.784 113.64,-44.784 ; -54,-39.62 113.69,-39.62 ; -54,-34.455 -54,-49.949 47.727,-49.949 113.69,-49.949 113.69,-34.455 -53.988,-34.455 -53.988,-49.949 -13.97,-49.949 ; 8.611,-49.949 8.611,-34.455 ; 40.792,-39.62 40.792,-34.455 ; 62.128,-39.62 62.128,-34.455 ; 77.927,-50.114 77.927,-44.962
  text "COMPONENTS MARKED 'DNP' SHOULD NOT BE POPULATED." at -17.285,-29.248 h1.52
  text "ASSEMBLY VARIANT:" at -17.297,-32.182 h1.52
  text ".VariantName" at 9.017,-32.182 h1.52
  text "PCB VIEWED FROM TOP SIDE" at -52.387,-37.812 h1.52
  text "BOARD #:" at 10.516,-37.812 h1.52
  text "'.PRJ_Number'" at 24.371,-37.812 h1.52
  text "REV:" at 45.822,-37.812 h1.52
  text "'.SCH_Rev'" at 53.226,-37.812 h1.52
  text "SVN REV:" at 67.107,-37.812 h1.52
  text ".VersionControl_RevNumber" at 79.959,-37.812 h1.52
  text "TID #:" at 10.516,-42.977 h1.52
  text "'.PRJ_Number'" at 24.371,-42.977 h1.52
  text "PLOT NAME =" at -52.387,-48.192 h1.52
  text ".plot_File_Name" at -31.928,-48.192 h1.52
  text "GENERATED    :" at 10.566,-48.192 h1.52
  text ".Print_Date" at 32.652,-48.192 h1.52
  text ".Print_Time" at 51.168,-48.192 h1.52
  text "TEXAS INSTRUMENTS" at 83.287,-48.192 h1.52
M9 Title Sheet:
  drawing of 57 lines, arcs and shapes, not listed
  text "1" at -27.792,182.969 h1.78
  text "2" at 35.598,182.969 h1.78
  text "3" at 98.827,182.969 h1.78
  text "4" at 162.497,182.969 h1.78
  text "5" at 225.971,182.969 h1.78
  text "6" at 289.598,182.969 h1.78
  text "A" at -57.163,153.937 h1.78
  text "A" at 318.757,153.937 h1.78
  text "B" at -57.163,93.485 h1.78
  text "B" at 318.757,93.485 h1.78
  text "C" at -57.163,33.16 h1.78
  text "C" at 318.757,33.16 h1.78
  text "PROJECT TITLE:" at 241.541,-14.11 h1.14
  text "'.PRJ_Title'" at 242.811,-17.496 h1.78
  text "DESIGNED FOR:" at 241.541,-21.755 h1.14
  text "Public" at 242.811,-25.311 h1.78
  text "D" at -57.163,-27.038 h1.78
  text "D" at 318.757,-27.038 h1.78
  text "FILE NAME:" at 241.541,-29.375 h1.14
  text "'.Pcb_File_Name_No_Path'" at 242.811,-32.423 h1.78
  text "Texas Instruments (TI) and/or its licensors do not warrant the accuracy or completeness of this specification" at 115.316,-36.534 h1.14
  text "ENGINEER:" at 241.541,-36.741 h1.14
  text "LAYOUT BY:" at 279.768,-36.741 h1.14
  text "or any information contained therein. TI and/or its licensors do not warrant that this design will meet" at 114.173,-39.395 h1.14
  text "'.PRJ_Engineer'" at 242.811,-40.678 h1.78
  text "'.PRJ_Engineer'" at 281.051,-40.678 h1.78
  text "the specifications, will be suitable for your application or fit for any particular purpose, or will operate in" at 114.173,-42.257 h1.14
  text ".Layer_Name" at -31.928,-42.964 h1.52
  text "ALTIUM DESIGNER VERSION:" at 279.768,-44.615 h1.14
  text "an implementation. TI and/or its licensors do not warrant that the design is production worthy. You should" at 114.173,-45.119 h1.14
  text "completely validate and test your design implementation to confirm the system functionality for your application." at 115.316,-47.981 h1.14
  text ".print_Scale" at 242.811,-48.002 h1.78
  text "17.1" at 281.051,-48.002 h1.78
  text "1" at -27.792,-53.251 h1.78
  text "2" at 35.598,-53.251 h1.78
  text "3" at 98.827,-53.251 h1.78
  text "4" at 162.497,-53.251 h1.78
  text "5" at 225.971,-53.251 h1.78
  text "6" at 289.598,-53.251 h1.78
M10 Fab Notes:
  drawing of 189 lines, arcs and shapes, not listed
  text "DESIGN INFORMATION" at 267.92,140.289 h1.52
  text "MIN. TRACK WIDTH:" at 251.548,136.933 h1.52
  text "6" at 279.392,136.933 h1.52
  text "MIL" at 283.323,136.933 h1.52
  text "MIN. CLEARANCE:" at 251.548,133.78 h1.52
  text "0.2" at 277.868,133.78 h1.52
  text "mm" at 283.323,133.78 h1.52
  text "MIN. VIA PAD SIZE:" at 251.548,130.627 h1.52
  text "20" at 278.631,130.627 h1.52
  text "MIL" at 283.323,130.627 h1.52
  text "0.05mm (2MIL)" at 269.201,127.328 h1.52
  text "MINIMUM ANNULAR RING" at 243.185,127.119 h1.52
  text "EXTERNAL" at 287.184,127.119 h1.52
  text "PER" at 248.265,124.322 h1.52
  text "IPC-D-275 CLASS 2 LEVEL C" at 253.853,124.321 h1.52
  text "MIL, HOLES" at 291.654,121.769 h1.52
  text "+/-" at 281.686,121.551 h1.52
  text "+/-" at 303.378,121.551 h1.52
  text "REGISTRATION TOLERANCES:" at 243.185,121.524 h1.52
  text "METAL" at 273.66,121.524 h1.52
  text "5" at 288.295,121.524 h1.52
  text "3" at 309.453,121.524 h1.52
  text "MIL" at 312.406,121.524 h1.52
  text "HOLE SIZE TOLERANCE (UNLESS OTHERWISE SPECIFIED):" at 243.185,119.027 h1.52
  text "+/-" at 303.378,118.954 h1.52
  text "3" at 309.453,118.927 h1.52
  text "MIL" at 312.406,118.927 h1.52
  text "MATERIAL:" at 241.286,115.431 h1.52
  text "FR-4 High Tg" at 266.342,112.166 h1.52
  text "X" at 285.14,111.938 h1.52
  text "Flex (Polymide)" at 297.078,111.938 h1.52
  text "FR-408" at 251.98,111.849 h1.52
  text "OTHER" at 289.775,111.849 h1.52
  text "6.4 MIL (0.163mm) +/-10%" at 260.11,108.216 h1.52
  text "X" at 257.06,108.153 h1.52
  text "THICKNESS:" at 243.185,108.007 h1.52
  text "OTHER" at 292.747,108.007 h1.52
  text "TOLERANCE:" at 243.185,104.494 h1.52
  text "X" at 264.731,104.494 h1.52
  text "ANSI IPC-6012 TYPE 3 CLASS 2" at 269.252,104.494 h1.52
  text "OTHER +/-" at 269.252,100.831 h1.52
  text "BOW & TWIST:" at 243.185,97.143 h1.52
  text "X" at 264.731,97.143 h1.52
  text "ANSI IPC-6012 TYPE 3 CLASS 2" at 269.252,97.143 h1.52
  text "OTHER +/-" at 269.252,93.417 h1.52
  text "DRILLING:" at 241.286,90.1 h1.52
  text "NC_DRILL FILES" at 286.016,87.428 h1.52
  text "REFERENCE:" at 243.185,87.328 h1.52
  text "X" at 259.879,87.325 h1.52
  text "AS SHOWN" at 264.4,87.328 h1.52
  text "X" at 282.765,87.328 h1.52
  text "OTHER" at 293.585,83.715 h1.52
  text "PTH COPPER THICKNESS:" at 243.177,83.625 h1.52
  text "X" at 272.114,83.625 h1.52
  text "1 mil" at 275.365,83.625 h1.52
  text "BOARD FINISH:" at 241.286,79.876 h1.52
  text "SILKSCREEN:" at 245.229,77.079 h1.52
  text "X" at 269.557,77.079 h1.52
  text "TOP" at 272.528,77.079 h1.52
  text "X" at 282.511,77.079 h1.52
  text "BOTTOM" at 285.508,77.079 h1.52
  text "SILKSCREEN COLOR:" at 245.229,73.137 h1.52
  text "X" at 269.531,73.137 h1.52
  text "WHITE" at 272.528,73.137 h1.52
  text "OTHER" at 285.508,73.137 h1.52
  text "GREEN" at 275.856,69.493 h1.52
  text "OTHER" at 291.553,69.493 h1.52
  text "X" at 287.655,69.469 h1.52
  text "SOLDER RESIST COLOR:" at 245.229,69.319 h1.52
  text "N/A" at 305.227,69.302 h1.52
  text "X" at 272.859,65.575 h1.52
  text "MATTE" at 275.856,65.575 h1.52
  text "SEMI-GLOSS" at 291.541,65.559 h1.52
  text "IMMERSION GOLD (ENIG)" at 268.236,61.187 h1.52
  text "ENEPIG" at 302.209,61.004 h1.52
  text "SURFACE FINISH:" at 241.286,60.978 h1.52
  text "X" at 263.715,60.978 h1.52
  text "IMM. TIN/SILVER OR EQUIV" at 249.657,57.49 h1.52
  text "OTHER" at 286.016,57.39 h1.52
  text "ARRAY/PANEL:" at 241.286,53.444 h1.52
  text "CUT AND TRIM PER M1 BOARD OUTLINE" at 268.236,53.235 h1.52
  text "N.C. ROUTE" at 268.236,49.781 h1.52
  text "X" at 285.711,49.781 h1.52
  text "V. SCORE" at 290.232,49.781 h1.52
  text "CERTIFICATION:" at 241.286,46.502 h1.52
  text "MATERIALS AND WORKMANSHIP FOR ALL PCBS" at 259.701,46.502 h1.52
  text "TO MEET OR EXCEED THE REQUIREMENTS OF:" at 259.701,44.112 h1.52
  text "X" at 250.494,40.845 h1.52
  text "ANSI IPC-A-600F CLASS ->" at 253.745,40.845 h1.52
  text "X" at 295.604,40.845 h1.52
  text "2" at 298.398,40.845 h1.52
  text "1" at 290.397,40.807 h1.52
  text "3" at 307.39,40.807 h1.52
  text "X" at 271.119,37.094 h1.52
  text "RoHS" at 274.37,37.094 h1.52
  text "OTHER" at 290.738,37.094 h1.52
  text "PER ORDER" at 300.823,37.094 h1.52
  text "ALL BOARDS MUST MEET OR EXCEED UL94-V0 REQUIREMENTS." at 241.986,33.187 h1.52
  text "PCB MUST BEAR THE UL94V-0 UL REGISTERED MATERIAL ID NUMBER" at 241.986,30.239 h1.52
  text "ADDITIONAL REQUIREMENTS:" at 241.286,25.935 h1.52
  text "MICROSECTION:" at 243.185,23.214 h1.52
  text "YES" at 266.191,23.214 h1.52
  text "REQUIRED" at 288.073,19.548 h1.52
  text "BARE BOARD ELEC. TEST:" at 243.185,19.476 h1.52
  text "NONE" at 276.351,19.476 h1.52
  text "X" at 285.076,19.476 h1.52
  text "PER ORDER" at 303.11,19.476 h1.52
  text "XX MIL VIAS REQUIRE NON-CONDUCTIVE FILL AND PLANARIZE" at 247.456,14.27 h1.5
  text "XX MIL VIAS REQUIRE CONDUCTIVE FILL AND PLANARIZE" at 247.66,11.629 h1.52
  text "OUTER XX MIL TRACES REQUIRE 50 OHM SINGLE-ENDED IMPEDANCE" at 247.635,7.479 h1.47
  text "LAYER 2 & 3 (INNER LAYERS) XX MIL WIDE, XX MIL SPACE / TRACES REQUIRE 100 OHM DIFFERENTIAL IMPEDANCE" at 247.431,1.492 h1.52
  text ".Layer_Name" at -31.928,-42.964 h1.52
M11 Gerber Information:
  lines w0.254: -54,-44.784 113.64,-44.784 ; -54,-39.62 113.69,-39.62 ; -54,-34.455 -54,-49.949 47.727,-49.949 113.69,-49.949 113.69,-34.455 -53.988,-34.455 -53.988,-49.949 -13.97,-49.949 ; 8.611,-49.949 8.611,-34.455 ; 40.792,-39.62 40.792,-34.455 ; 62.128,-39.62 62.128,-34.455 ; 77.927,-50.114 77.927,-44.962
  text "BOARD #:" at 10.516,-37.812 h1.52
  text "REV:" at 45.822,-37.812 h1.52
  text "SVN REV:" at 67.107,-37.812 h1.52
  text ".VersionControl_RevNumber" at 79.959,-37.812 h1.52
  text "LAYER NAME =" at -52.387,-42.964 h1.52
  text "TID #:" at 10.516,-42.977 h1.52
  text "PLOT NAME =" at -52.387,-48.192 h1.52
  text ".plot_File_Name" at -31.928,-48.192 h1.52
  text "GENERATED    :" at 10.566,-48.192 h1.52
  text ".Print_Date" at 32.652,-48.192 h1.52
  text ".Print_Time" at 51.168,-48.192 h1.52
  text "TEXAS INSTRUMENTS" at 83.287,-48.192 h1.52
M12 Stackup:
  drawing of 232 lines, arcs and shapes, not listed
  text "Layer" at 89.315,30.556 h1.52
  text "Name" at 99.727,30.556 h1.52
  text "Material" at 123.342,30.556 h1.52
  text "Thickness" at 139.34,30.556 h1.52
  text "Constant" at 155.846,30.556 h1.52
  text "Stiffened" at 170.321,30.556 h1.52
  text "Flex" at 186.065,30.556 h1.52
  text "Top Overlay" at 99.727,27.508 h1.52
  text "Top Solder" at 99.727,24.46 h1.52
  text "Polymide" at 123.342,24.46 h1.52
  text "1.00mil" at 139.34,24.46 h1.52
  text "3.3" at 155.846,24.46 h1.52
  text "1" at 89.315,21.412 h1.52
  text "Top Layer" at 99.727,21.412 h1.52
  text "0.70mil" at 139.34,21.412 h1.52
  text "Stiffener" at 99.727,18.364 h1.52
  text "Polyimide" at 123.342,18.364 h1.52
  text "5.00mil" at 139.34,18.364 h1.52
  text "4.2" at 155.846,18.364 h1.52
  text "Flex Substrate" at 99.727,15.316 h1.52
  text "Polymide" at 123.342,15.316 h1.52
  text "3.00mil" at 139.34,15.316 h1.52
  text "3.3" at 155.846,15.316 h1.52
  text "2" at 89.315,12.268 h1.52
  text "Bottom Layer" at 99.727,12.268 h1.52
  text "0.70mil" at 139.34,12.268 h1.52
  text "Bottom Solder" at 99.727,9.22 h1.52
  text "Polyimide" at 123.342,9.22 h1.52
  text "1.00mil" at 139.34,9.22 h1.52
  text "3.3" at 155.846,9.22 h1.52
  text "Bottom Overlay" at 99.727,6.172 h1.52
  text ".Layer_Name" at -31.928,-42.964 h1.52
M13 Component Bodies Top:
  text ".Layer_Name" at -31.928,-42.964 h1.52
M14 Component Bodies Bottom:
  text ".Layer_Name" at -31.928,-42.964 h1.52
M15 Courtyards Top:
  text ".Layer_Name" at -31.928,-42.964 h1.52
M16 Courtyards Bottom:
  text ".Layer_Name" at -31.928,-42.964 h1.52
Drill Drawing:
  circle w0.254: c89.655,61.543 r0.702
  lines w0.254: 88.953,41.895 89.655,42.246 90.357,41.895 90.006,42.597 90.357,43.299 89.655,42.948 88.953,43.299 89.304,42.597 88.953,41.895 ; 88.953,45.755 89.655,45.053 90.357,45.755 89.655,46.456 88.953,45.755 ; 88.953,48.561 89.304,48.561 89.304,48.211 90.006,48.211 90.006,48.561 90.357,48.561 90.357,49.263 90.006,49.263 90.006,49.614 89.304,49.614 89.304,49.263 88.953,49.263 88.953,48.561 ; 88.953,52.772 90.357,52.772 89.655,51.368 88.953,52.772 ; 88.953,54.526 88.953,54.877 89.304,55.228 88.953,55.579 88.953,55.93 89.304,55.93 89.655,55.579 90.006,55.93 90.357,55.93 90.357,55.579 90.006,55.228 90.357,54.877 90.357,54.526 90.006,54.526 89.655,54.877 89.304,54.526 88.953,54.526 ; 88.953,57.684 90.357,57.684 90.357,59.087 88.953,59.087 88.953,57.684 ; 88.953,64.35 89.304,64.35 89.655,63.999 90.006,64.35 90.357,64.35 90.006,64.701 90.357,65.052 90.006,65.052 89.655,65.403 89.304,65.052 88.953,65.052 89.304,64.701 88.953,64.35
  lines w0.305: 87.681,40.948 169.775,40.948 ; 87.681,66.21 169.775,66.21 ; 96.266,37.79 96.266,69.367 ; 104.701,37.79 104.701,69.367 ; 120.872,37.79 120.872,69.367 ; 127.455,37.79 127.455,69.367 ; 136.986,37.79 136.986,69.367 ; 155.384,37.79 155.384,69.367 ; 87.681,37.79 169.775,37.79 169.775,69.367 87.681,69.367 87.681,37.79
  text "Symbol" at 89.575,67.157 h1.83
  text "Quantity" at 97.213,67.157 h1.83
  text "Finished Hole Size" at 105.648,67.157 h1.83
  text "Plated" at 121.819,67.157 h1.83
  text "Hole Type" at 128.402,67.157 h1.83
  text "Drill Layer Pair" at 137.933,67.157 h1.83
  text "Hole Tolerance" at 156.331,67.157 h1.83
  text "3" at 97.213,63.999 h1.52
  text "39.00mil (0.991mm)" at 105.648,63.999 h1.52
  text "NPTH" at 121.819,63.999 h1.52
  text "Round" at 128.402,63.999 h1.52
  text "Top Layer - Bottom Layer" at 137.933,63.999 h1.52
  text "115" at 97.213,60.842 h1.52
  text "5.91mil (0.150mm)" at 105.648,60.842 h1.52
  text "PTH" at 121.819,60.842 h1.52
  text "Round" at 128.402,60.842 h1.52
  text "Top Layer - Bottom Layer" at 137.933,60.842 h1.52
  text "2" at 97.213,57.684 h1.52
  text "8.00mil (0.203mm)" at 105.648,57.684 h1.52
  text "PTH" at 121.819,57.684 h1.52
  text "Round" at 128.402,57.684 h1.52
  text "Top Layer - Bottom Layer" at 137.933,57.684 h1.52
  text "1" at 97.213,54.526 h1.52
  text "10.00mil (0.254mm)" at 105.648,54.526 h1.52
  text "PTH" at 121.819,54.526 h1.52
  text "Round" at 128.402,54.526 h1.52
  text "Top Layer - Bottom Layer" at 137.933,54.526 h1.52
  text "5" at 97.213,51.368 h1.52
  text "12.00mil (0.305mm)" at 105.648,51.368 h1.52
  text "PTH" at 121.819,51.368 h1.52
  text "Round" at 128.402,51.368 h1.52
  text "Top Layer - Bottom Layer" at 137.933,51.368 h1.52
  text "4" at 97.213,48.211 h1.52
  text "15.00mil (0.381mm)" at 105.648,48.211 h1.52
  text "PTH" at 121.819,48.211 h1.52
  text "Round" at 128.402,48.211 h1.52
  text "Top Layer - Bottom Layer" at 137.933,48.211 h1.52
  text "1" at 97.213,45.053 h1.52
  text "20.00mil (0.508mm)" at 105.648,45.053 h1.52
  text "PTH" at 121.819,45.053 h1.52
  text "Round" at 128.402,45.053 h1.52
  text "Top Layer - Bottom Layer" at 137.933,45.053 h1.52
  text "1" at 97.213,41.895 h1.52
  text "40.00mil (1.016mm)" at 105.648,41.895 h1.52
  text "PTH" at 121.819,41.895 h1.52
  text "Round" at 128.402,41.895 h1.52
  text "Top Layer - Bottom Layer" at 137.933,41.895 h1.52
  text "132 Total" at 97.213,38.737 h1.52
  text "'.PRJ_Number'" at 24.371,-37.812 h1.52
  text ".Layer_Name" at -31.928,-42.964 h1.52
Mechanical 17:
  text ".Layer_Name" at -31.928,-42.964 h1.52
Mechanical 18:
  text ".Layer_Name" at -31.928,-42.964 h1.52
Mechanical 19:
  text ".Layer_Name" at -31.928,-42.964 h1.52

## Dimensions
19.05,28.345 to 0,28.345 on M2 Board Dimensions
16.51,30.885 to 16.51,0 on M2 Board Dimensions
-46.584,-31.318 to -21.184,-31.318 on M2 Board Dimensions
